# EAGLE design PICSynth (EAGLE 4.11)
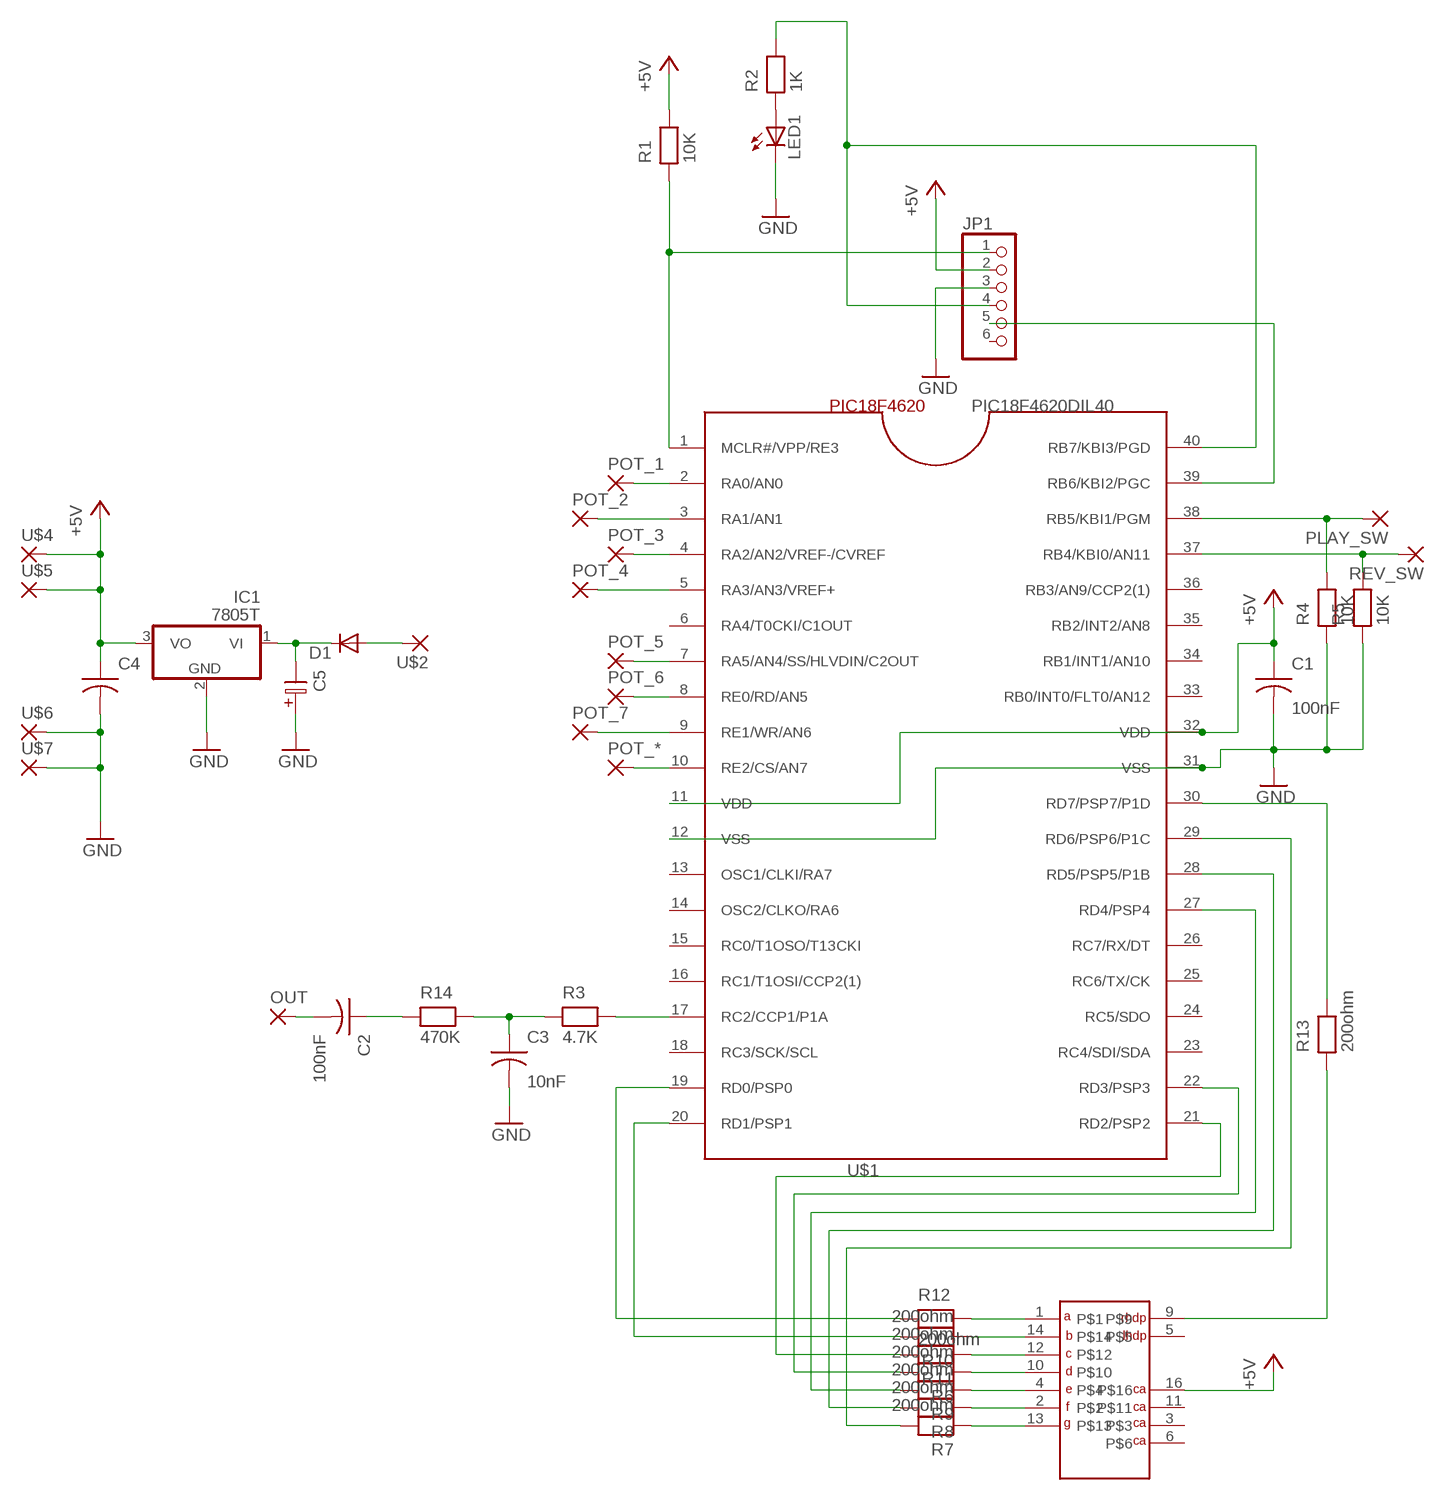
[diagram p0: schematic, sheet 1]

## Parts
C1  100nF  CAP-5  [C-5]
C2  100nF  CAP-5  [C-5]
C3  10nF  CAP-5  [C-5]
C4  CAP-5  [C-5]
C5  ELC-25  [E-25]
D1  DIODE-D-10  [D-10]
IC1  7805T  [TO220H]
JP1  PINHD-1X6  [1X06]
LED1  LED5MM  [LED5MM]
OUT  PAD  [PAD]
PLAY_SW  PAD  [PAD]
POT_1  PAD  [PAD]
POT_2  PAD  [PAD]
POT_3  PAD  [PAD]
POT_4  PAD  [PAD]
POT_5  PAD  [PAD]
POT_6  PAD  [PAD]
POT_7  PAD  [PAD]
POT_*  PAD  [PAD]
R1  10K  RESEU-1010  [R-10]
R2  1K  RESEU-1010  [R-10]
R3  4.7K  RESEU-1010  [R-10]
R4  10K  RESEU-1010  [R-10]
R5  10K  RESEU-1010  [R-10]
R6  200ohm  RESEU-1010  [R-10]
R7  200ohm  RESEU-1010  [R-10]
R8  200ohm  RESEU-1010  [R-10]
R9  200ohm  RESEU-1010  [R-10]
R10  200ohm  RESEU-1010  [R-10]
R11  200ohm  RESEU-1010  [R-10]
R12  200ohm  RESEU-1010  [R-10]
R13  200ohm  RESEU-1010  [R-10]
R14  470K  RESEU-1010  [R-10]
REV_SW  PAD  [PAD]
U$1  PIC18F4620DIL40  [DIL40]
U$2  PAD  [PAD]
U$3  LA8071  [LA8071]
U$4  PAD  [PAD]
U$5  PAD  [PAD]
U$6  PAD  [PAD]
U$7  PAD  [PAD]

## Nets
+5V: C1.1 C4.1 IC1.3(VO) JP1.2 R1.2 U$1.11(VDD) U$1.32(VDD) U$3.16 U$4.1(P) U$5.1(P)
GND: C1.2 C3.2 C4.2 C5.1 IC1.2(GND) JP1.3 LED1.K(C) R4.1 R5.1 U$1.12(VSS) U$1.31(VSS) U$6.1(P) U$7.1(P)
N$1: JP1.1 R1.1 U$1.1(MCLR#/VPP/RE3)
N$2: C2.1 R14.1
N$3: LED1.A R2.1
N$4: JP1.4 R2.2 U$1.40(RB7/KBI3/PGD)
N$5: JP1.5 U$1.39(RB6/KBI2/PGC)
N$6: POT_1.1(P) U$1.2(RA0/AN0)
N$7: POT_2.1(P) U$1.3(RA1/AN1)
N$8: POT_3.1(P) U$1.4(RA2/AN2/VREF-/CVREF)
N$9: POT_4.1(P) U$1.5(RA3/AN3/VREF+)
N$10: POT_5.1(P) U$1.7(RA5/AN4/SS/HLVDIN/C2OUT)
N$11: POT_6.1(P) U$1.8(RE0/RD/AN5)
N$12: POT_7.1(P) U$1.9(RE1/WR/AN6)
N$13: POT_*.1(P) U$1.10(RE2/CS/AN7)
N$14: R3.2 U$1.17(RC2/CCP1/P1A)
N$15: C3.1 R3.1 R14.2
N$16: C2.2 OUT.1(P)
N$17: PLAY_SW.1(P) R4.2 U$1.38(RB5/KBI1/PGM)
N$18: R5.2 REV_SW.1(P) U$1.37(RB4/KBI0/AN11)
N$19: R12.2 U$3.1
N$20: R10.1 U$3.14
N$21: R11.1 U$3.12
N$22: R9.1 U$3.4
N$23: R8.1 U$3.2
N$24: R7.1 U$3.13
N$25: R6.1 U$3.10
N$26: R13.2 U$1.30(RD7/PSP7/P1D)
N$27: R12.1 U$1.19(RD0/PSP0)
N$28: R10.2 U$1.20(RD1/PSP1)
N$29: R11.2 U$1.21(RD2/PSP2)
N$30: R6.2 U$1.22(RD3/PSP3)
N$31: R9.2 U$1.27(RD4/PSP4)
N$32: R8.2 U$1.28(RD5/PSP5/P1B)
N$33: R7.2 U$1.29(RD6/PSP6/P1C)
N$34: R13.1 U$3.9
N$40: C5.2 D1.C IC1.1(VI)
N$41: D1.A U$2.1(P)
Unconnected: JP1.6 U$1.6(RA4/T0CKI/C1OUT) U$1.13(OSC1/CLKI/RA7) U$1.14(OSC2/CLKO/RA6) U$1.15(RC0/T1OSO/T13CKI) U$1.16(RC1/T1OSI/CCP2(1)) U$1.18(RC3/SCK/SCL) U$1.23(RC4/SDI/SDA) U$1.24(RC5/SDO) U$1.25(RC6/TX/CK) U$1.26(RC7/RX/DT) U$1.33(RB0/INT0/FLT0/AN12) U$1.34(RB1/INT1/AN10) U$1.35(RB2/INT2/AN8) U$1.36(RB3/AN9/CCP2(1)) U$3.3 U$3.5 U$3.6 U$3.11

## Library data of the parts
C1-C4 = discrete:CAP-5
C5 = discrete:ELC-25
D1 = diode:DIODE-: DIODE
IC1 = linear:78*: Positive VOLTAGE REGULATOR
JP1 = microchip:PINHD-1X6: PIN HEADER
LED1 = led:LED: LED
OUT PLAY_SW POT_1-POT_7 POT_* REV_SW U$2 U$4-U$7 = custom:PAD
R1-R14 = discrete:RESEU-10
U$1 = microchip:PIC18F4620
U$3 = custom:LA8071

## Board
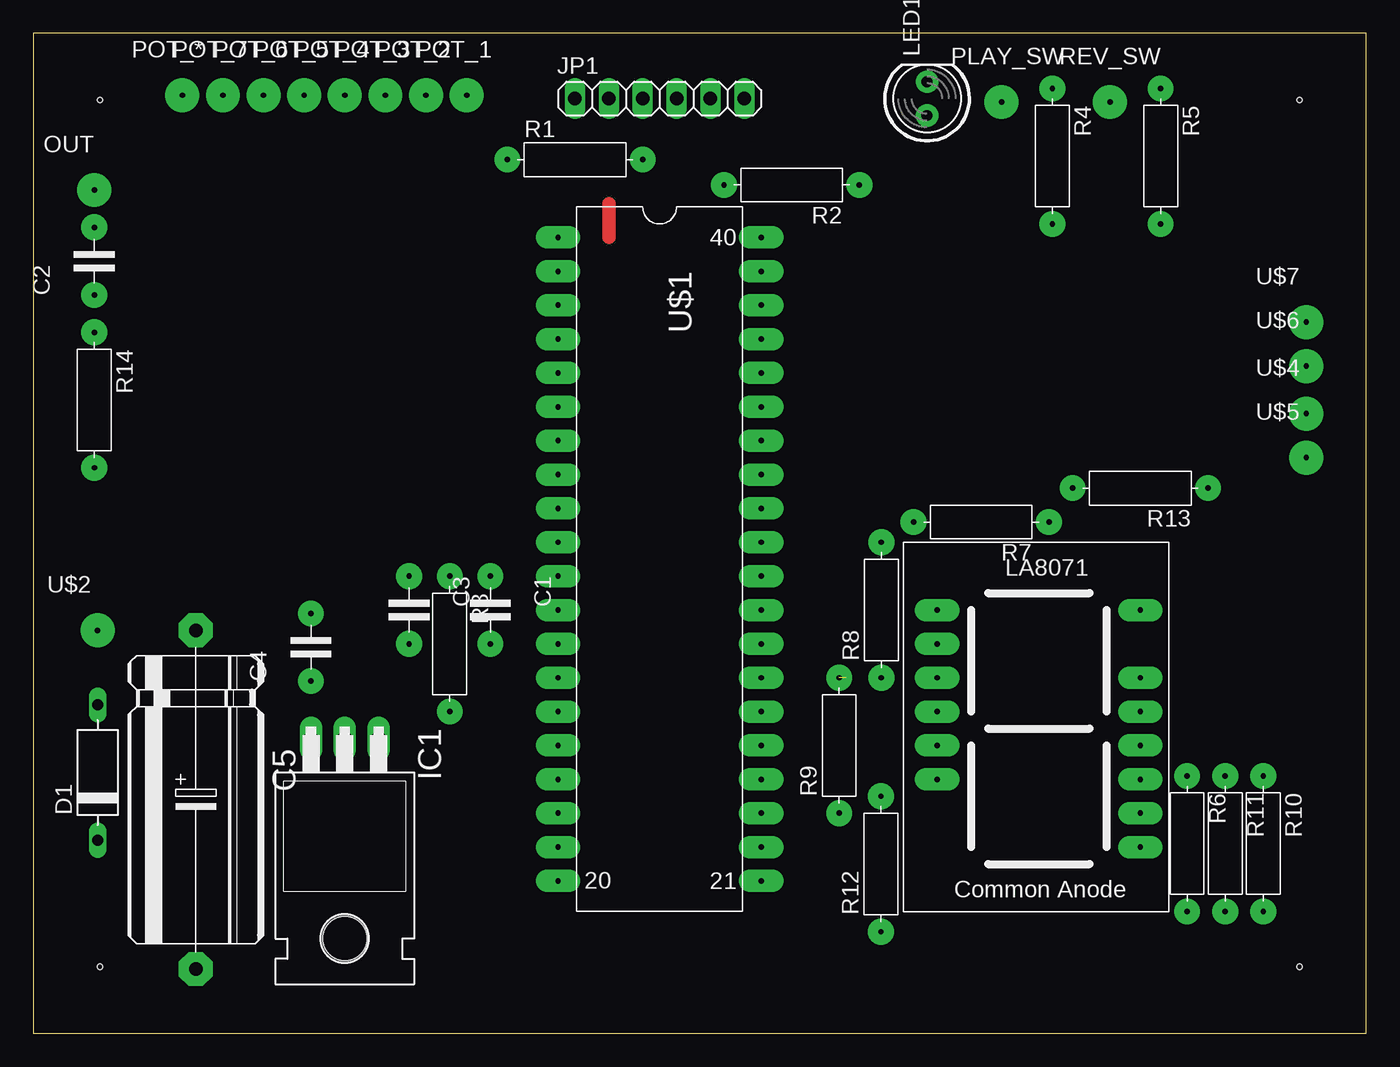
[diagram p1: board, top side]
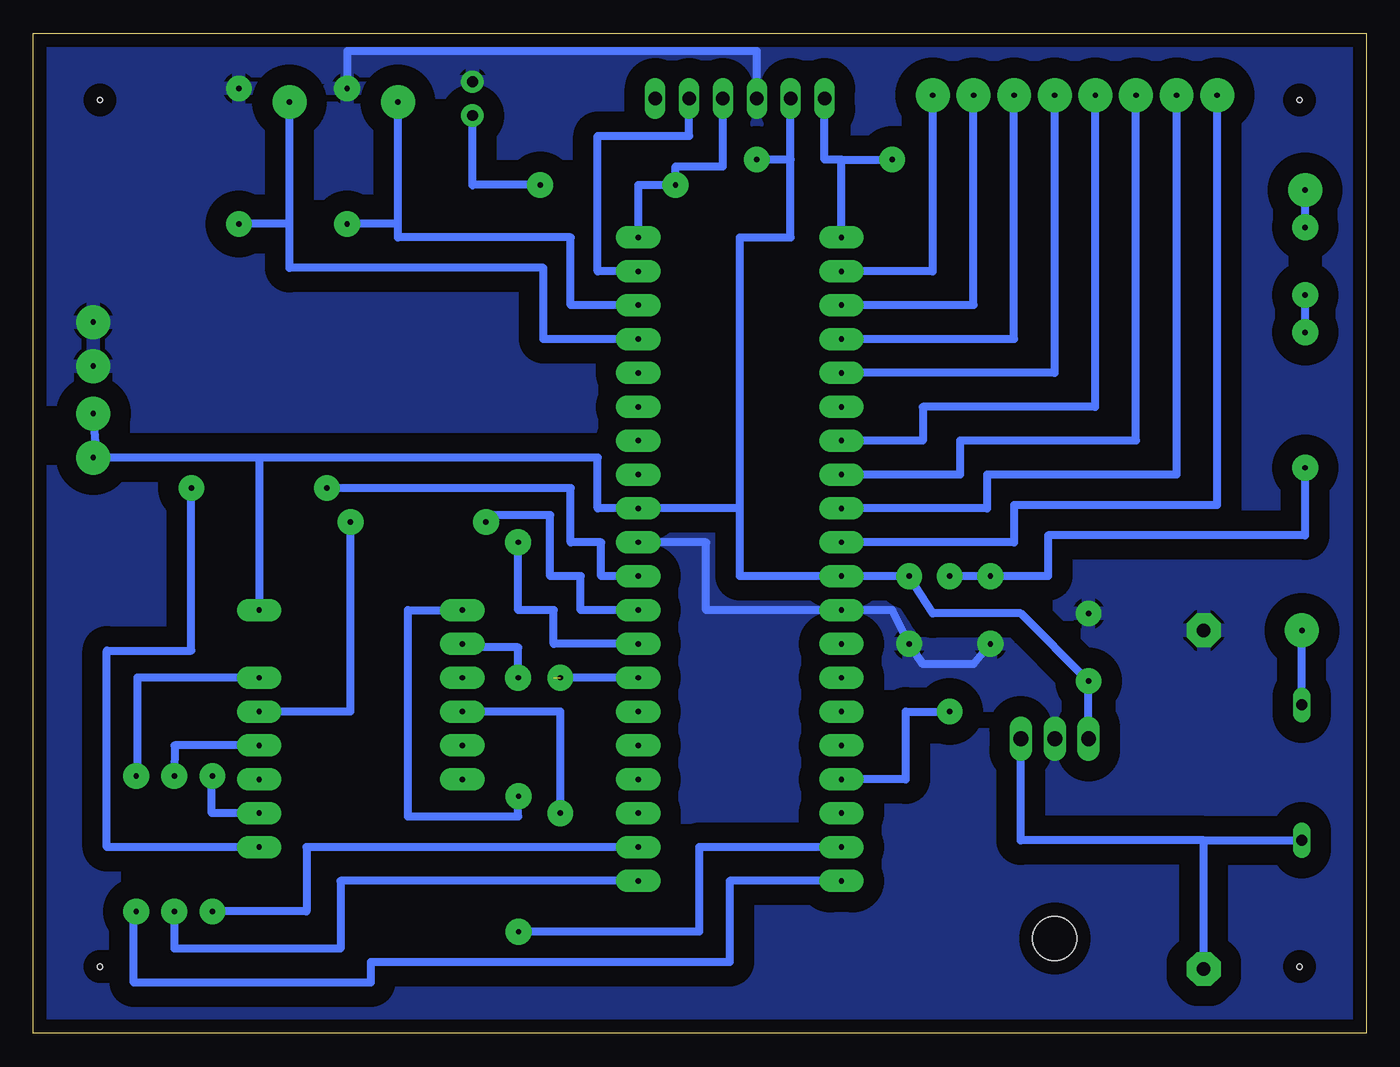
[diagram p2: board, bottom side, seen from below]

Size 100 x 75 mm. Coordinates in mm from the lower left corner, seen from the top.
Outline: 0,0 100,0 100,75 0,75 0,0
Copper layers (1*16): Top 0.035mm / dielectric 1.5mm / Bottom 0.035mm
Design rules "DesktopScienceStandard": minimum track width 10mil, minimum drill 24mil, track to track 60mil, track to pad 40mil, pad to pad 20mil, via to via 40mil, smd to smd 8mil, copper to edge 40mil, drill to drill 20mil, minimum pad ring 10mil, minimum via ring 8mil, stop-mask expansion 20mil, vias tented up to drill 0mil, thermal gap 10mil
Holes 0.4 mm at 5,5 5,70 95,70 95,5

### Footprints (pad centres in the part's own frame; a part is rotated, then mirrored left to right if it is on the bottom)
C-5 = drill 0.406 pad 1.93 round: 1 -2.54,0; 2 2.54,0
E-25 = drill 1.016 pad 2.54 octagon: 1 0,0; 2 25.4,0
D-10 = drill 0.813 long: A 5.08,0; C -5.08,0
TO220H = drill 1.118 long: 1 -2.54,-10.16; 2 0,-10.16; 3 2.54,-10.16 | hole 3.302: 0,4.826
1X06 = drill 1.016 long: 1 -6.35,0; 2 -3.81,0; 3 -1.27,0; 4 1.27,0; 5 3.81,0; 6 6.35,0
LED5MM = drill 0.813 pad 1.676 round: A -1.27,0; K 1.27,0
PAD = drill 0.406 pad 2.54 round: 1 0,0
R-10 = drill 0.406 pad 1.93 round: 1 -5.08,0; 2 5.08,0
DIL40 = drill 0.406 pad 1.676 long: 1 -24.13,-7.62; 2 -21.59,-7.62; 3 -19.05,-7.62; 4 -16.51,-7.62; 5 -13.97,-7.62; 6 -11.43,-7.62; 7 -8.89,-7.62; 8 -6.35,-7.62; 9 -3.81,-7.62; 10 -1.27,-7.62; 11 1.27,-7.62; 12 3.81,-7.62; 13 6.35,-7.62; 14 8.89,-7.62; 15 11.43,-7.62; 16 13.97,-7.62; 17 16.51,-7.62; 18 19.05,-7.62; 19 21.59,-7.62; 20 24.13,-7.62; 21 24.13,7.62; 22 21.59,7.62; 23 19.05,7.62; 24 16.51,7.62; 25 13.97,7.62; 26 11.43,7.62; 27 8.89,7.62; 28 6.35,7.62; 29 3.81,7.62; 30 1.27,7.62; 31 -1.27,7.62; 32 -3.81,7.62; 33 -6.35,7.62; 34 -8.89,7.62; 35 -11.43,7.62; 36 -13.97,7.62; 37 -16.51,7.62; 38 -19.05,7.62; 39 -21.59,7.62; 40 -24.13,7.62
LA8071 = drill 0.406 pad 1.676 long: 1 -7.62,8.89; 2 -7.62,6.35; 3 -7.62,3.81; 4 -7.62,1.27; 5 -7.62,-1.27; 6 -7.62,-3.81; 9 7.62,-8.89; 10 7.62,-6.35; 11 7.62,-3.81; 12 7.62,-1.27; 13 7.62,1.27; 14 7.62,3.81; 16 7.62,8.89

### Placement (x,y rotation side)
C1  34.29,31.75 270 top
C2  4.57,57.91 90 top
C3  28.19,31.75 270 top
C4  20.83,28.96 90 top
C5  12.19,30.23 270 top
D1  4.83,19.56 90 top
IC1  23.37,11.94 180 top
JP1  46.99,70.1 0 top
LED1  67.06,70.1 90 top
OUT  4.57,63.25 0 top
PLAY_SW  72.64,69.85 0 top
POT_1  32.51,70.36 0 top
POT_2  29.46,70.36 0 top
POT_3  26.42,70.36 0 top
POT_4  23.37,70.36 0 top
POT_5  20.32,70.36 0 top
POT_6  17.27,70.36 0 top
POT_7  14.22,70.36 0 top
POT_*  11.18,70.36 0 top
R1  40.64,65.53 0 top
R2  56.9,63.63 180 top
R3  31.24,29.21 270 top
R4  76.45,65.79 270 top
R5  84.58,65.79 270 top
R6  86.56,14.22 270 top
R7  71.12,38.35 180 top
R8  63.63,31.75 90 top
R9  60.46,21.59 90 top
R10  92.28,14.22 270 top
R11  89.42,14.22 270 top
R12  63.59,12.7 90 top
R13  83.06,40.89 180 top
R14  4.57,47.5 270 top
REV_SW  80.77,69.85 0 top
U$1  46.99,35.56 270 top
U$2  4.83,30.23 0 top
U$3  75.44,22.86 0 top
U$4  95.5,46.48 0 top
U$5  95.5,43.18 0 top
U$6  95.5,50.04 0 top
U$7  95.5,53.34 0 top

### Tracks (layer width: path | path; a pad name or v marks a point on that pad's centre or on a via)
+5V
  Bottom 0.61: 43.18,65.53 JP1.2 | 43.18,65.53 R1.2 | 46.99,39.37 46.99,34.29 U$1.11 C1.1 32.51,31.5 25.91,31.5 C4.1 IC1.3 | 46.99,39.37 U$1.32 57.66,39.37 57.66,43.18 83.06,43.18 | 43.18,65.53 43.18,59.69 46.99,59.69 46.99,39.37 | 83.06,43.18 U$3.16 | 83.06,43.18 U$5.1 95.25,43.43 U$4.1
GND
  Bottom 0.61: R4.1 76.45,73.66 45.72,73.66 JP1.3 | U$1.31 49.53,36.83 49.53,31.75 U$1.12 35.56,31.75 C1.2 33.27,27.69 29.46,27.69 C3.2
  pour Bottom: 0,0 0,75 100,75 100,0
N$1
  Bottom 0.61: 39.37,65.53 40.64,65.53 JP1.1 | 39.37,65.53 R1.1 | U$1.1 39.37,65.53
N$2
  Bottom 0.61: R14.1 C2.1
N$3
  Bottom 0.406: 67.06,63.63 67.06,63.5
  Bottom 0.61: LED1.A 67.06,63.63 R2.1
N$4
  Bottom 0.61: U$1.40 54.61,63.63 R2.2 51.82,65.02 48.26,65.02 JP1.4
N$5
  Bottom 0.61: U$1.39 57.66,57.15 57.66,67.31 50.8,67.31 JP1.5
N$6
  Bottom 0.61: POT_1.1 32.51,57.15 U$1.2
N$7
  Bottom 0.61: POT_2.1 29.46,54.61 U$1.3
N$8
  Bottom 0.61: POT_3.1 26.42,52.07 U$1.4
N$9
  Bottom 0.61: POT_4.1 23.37,49.53 U$1.5
N$10
  Bottom 0.61: U$1.7 33.27,44.45 33.27,46.99 20.32,46.99 POT_5.1
N$11
  Bottom 0.61: U$1.8 30.48,41.91 30.48,44.45 17.27,44.45 POT_6.1
N$12
  Bottom 0.61: U$1.9 28.45,39.37 28.45,41.91 14.22,41.91 POT_7.1
N$13
  Bottom 0.61: POT_*.1 11.18,39.62 26.42,39.62 26.42,36.83 U$1.10
N$14
  Bottom 0.61: R3.2 34.54,24.13 34.54,19.05 U$1.17
N$15
  Bottom 0.61: R3.1 C3.1 23.88,34.29 23.88,37.34 4.57,37.34 R14.2
N$16
  Bottom 0.61: C2.2 OUT.1
N$17
  Bottom 0.61: U$1.38 59.69,54.61 59.69,59.69 72.64,59.69 72.64,60.71 | 72.64,60.71 PLAY_SW.1 | 72.64,60.71 R4.2
N$18
  Bottom 0.61: U$1.37 61.72,52.07 61.72,57.4 80.77,57.4 80.77,60.71 | 80.77,60.71 REV_SW.1 | 80.77,60.71 R5.2
N$19
  Bottom 0.61: R12.2 63.63,16.26 71.88,16.26 71.88,31.75 U$3.1 67.56,31.75
N$20
  Bottom 0.61: U$3.14 92.2,26.67 92.2,19.3 R10.1
N$21
  Bottom 0.61: U$3.12 89.41,21.59 R11.1
N$22
  Bottom 0.61: R9.1 60.45,24.13 U$3.4
N$23
  Bottom 0.61: R8.1 63.63,28.96 67.82,28.96 U$3.2
N$24
  Bottom 0.61: R7.1 76.2,24.13 U$3.13
N$25
  Bottom 0.61: U$3.10 86.61,16.51 86.61,19.3 R6.1
N$26
  Bottom 0.61: U$1.30 57.4,34.29 57.4,36.83 59.69,36.83 59.69,40.89 R13.2
N$27
  Bottom 0.61: U$1.19 50.04,13.97 50.04,7.62 R12.1 64.01,7.62
N$28
  Bottom 0.61: U$1.20 47.75,11.43 47.75,5.33 74.68,5.33 74.68,3.81 92.46,3.81 92.46,8.89 92.2,9.14 R10.2
N$29
  Bottom 0.61: U$1.21 76.96,11.43 76.96,6.35 89.41,6.35 89.41,9.14 R11.2
N$30
  Bottom 0.61: U$1.22 79.5,13.97 79.5,9.14 R6.2 86.61,9.14
N$31  (1 unrouted)
  Bottom 0.61: U$1.27 60.96,26.67
N$32
  Bottom 0.61: U$1.28 60.96,29.21 60.96,31.75 63.63,31.75 R8.2 63.63,36.96
N$33
  Bottom 0.61: U$1.29 58.93,31.75 58.93,34.29 61.21,34.29 61.21,38.86 65.79,38.86 65.79,38.35 R7.2
N$34
  Bottom 0.61: R13.1 88.14,28.7 94.49,28.7 94.49,13.97 U$3.9
N$40
  Bottom 0.61: 12.19,14.48 D1.C | 12.19,14.48 25.91,14.48 IC1.1 | C5.2 12.19,14.48
N$41
  Bottom 0.61: D1.A U$2.1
